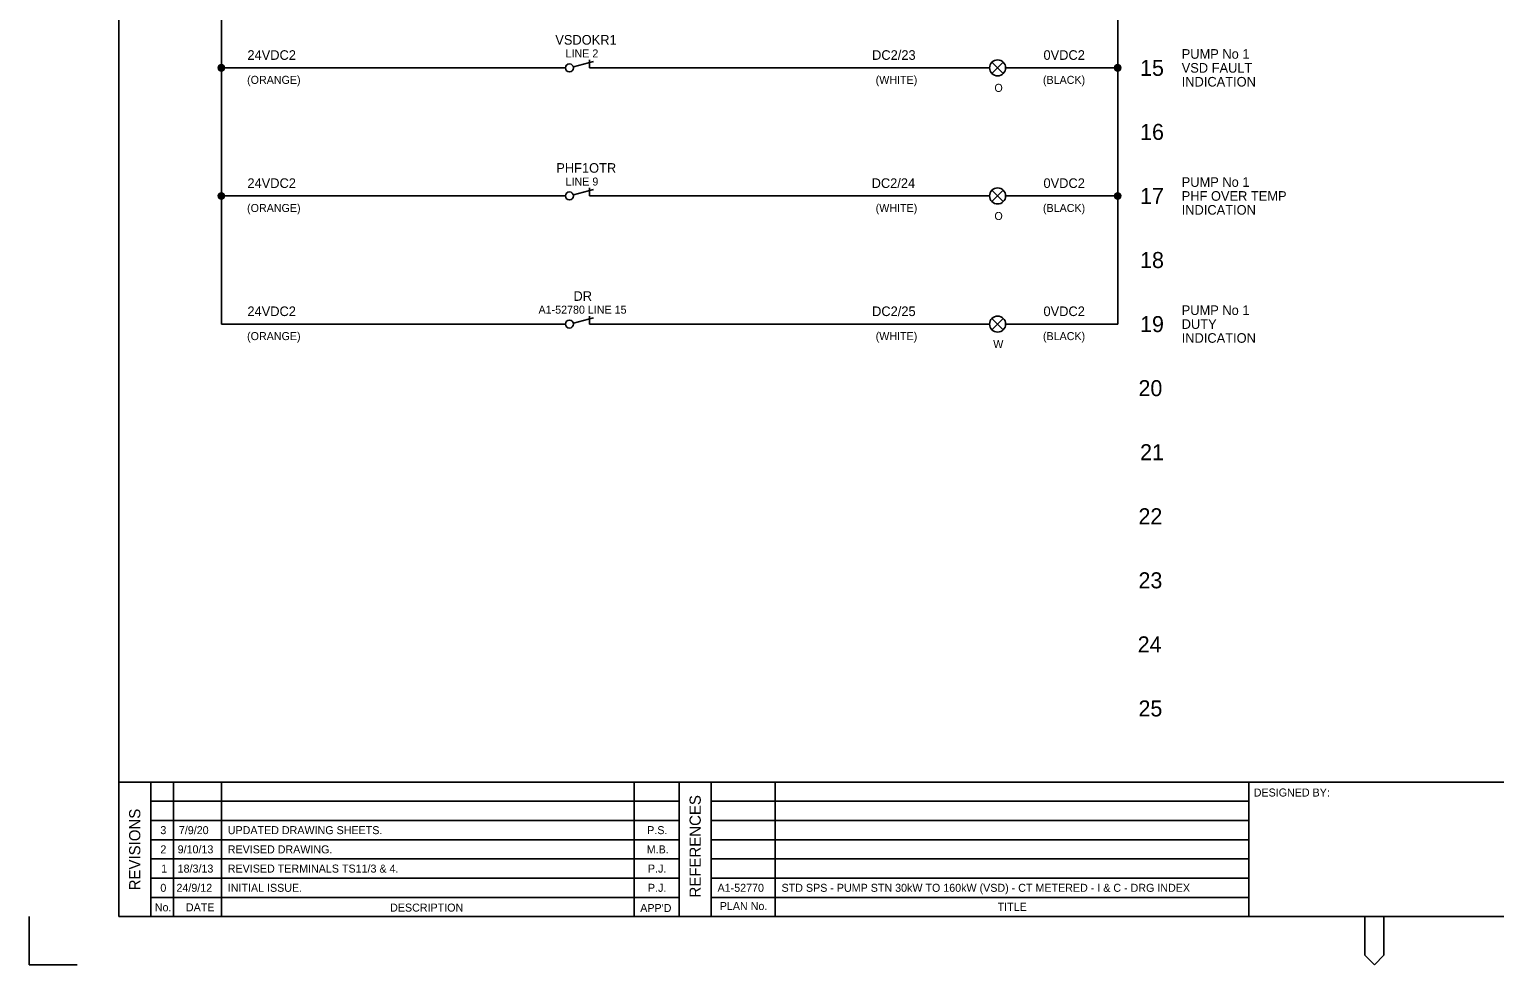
# Model space of a CAD drawing. Extents: x 0 to 841, y 0 to 594.
# Drawn here: x 0 to 457.8, y 0 to 292 of the extents above; entities that cross this region are included whole.
import ezdxf

# ---------------------------------------------------------------- set-up
doc = ezdxf.new("R2010")
doc.units = 0
for name, color, linetype in [('A1BORDER', 7, 'Continuous'), ('Level 1', 7, 'Continuous'), ('Level 10', 7, 'Continuous'), ('Level 5', 7, 'Continuous'), ('Level 6', 7, 'Continuous')]:
    doc.layers.add(name, color=color, linetype=linetype)

msp = doc.modelspace()

# ---------------------------------------------------------------- linework, layer by layer
at = {"layer": 'A1BORDER'}
for p, q in [((28, 581), (28, 15)), ((28, 57), (829, 57)), ((38, 15), (38, 57)), ((45, 15), (45, 57)), ((60, 15), (60, 57)), ((189, 15), (189, 57)), ((203, 15), (203, 57)), ((213, 15), (213, 57)), ((233, 15), (233, 57)), ((381, 15), (381, 57)), ((203, 51), (38, 51)), ((213, 51), (381, 51)), ((203, 45), (38, 45)), ((213, 45), (381, 45)), ((203, 39), (38, 39)), ((213, 39), (381, 39)), ((203, 33), (38, 33)), ((213, 33), (381, 33)), ((38, 27), (203, 27)), ((213, 27), (381, 27)), ((203, 21), (38, 21)), ((213, 21), (381, 21)), ((0, 0), (0, 15)), ((829, 15), (28, 15)), ((417.19, 15), (417.19, 3)), ((423.19, 15), (423.19, 3)), ((0, 0), (15, 0)), ((417.19, 3), (420.19, 0)), ((423.19, 3), (420.19, 0))]:
    msp.add_line(p, q, dxfattribs=at)
at = {"layer": 'Level 1'}
for p, q in [((60, 200), (60, 560)), ((340, 200), (340, 560)), ((60, 280), (167.5, 280)), ((175, 280), (177.5, 280)), ((305, 280), (340, 280)), ((60, 240), (167.5, 240)), ((175, 240), (177.5, 240)), ((305, 240), (340, 240)), ((60, 200), (167.5, 200)), ((175, 200), (177.5, 200)), ((305, 200), (340, 200))]:
    msp.add_line(p, q, dxfattribs=at)
at = {"layer": 'Level 10'}
for p, q in [((59.1, 280.44), (59.1, 279.56)), ((59.4, 280.8), (59.4, 279.2)), ((59.7, 280.95), (59.7, 279.05)), ((60, 281), (60, 279.01)), ((60.3, 280.95), (60.3, 279.05)), ((60.6, 280.8), (60.6, 279.2)), ((60.9, 280.44), (60.9, 279.56)), ((61, 280), (61, 280)), ((169.96, 280.32), (176.25, 282)), ((175, 282.5), (175, 280)), ((304.27, 281.77), (300.73, 278.23)), ((300.73, 281.77), (304.27, 278.23)), ((339.1, 280.44), (339.1, 279.56)), ((339.4, 280.8), (339.4, 279.2)), ((339.7, 280.95), (339.7, 279.05)), ((340, 281), (340, 279.01)), ((340.3, 280.95), (340.3, 279.05)), ((340.6, 280.8), (340.6, 279.2)), ((340.9, 280.44), (340.9, 279.56)), ((341, 280), (341, 280)), ((59.1, 240.44), (59.1, 239.56)), ((59.4, 240.8), (59.4, 239.2)), ((59.7, 240.95), (59.7, 239.05)), ((60, 241), (60, 239.01)), ((60.3, 240.95), (60.3, 239.05)), ((60.6, 240.8), (60.6, 239.2)), ((60.9, 240.44), (60.9, 239.56)), ((61, 240), (61, 240)), ((169.96, 240.32), (176.25, 242)), ((175, 242.5), (175, 240)), ((304.27, 241.77), (300.73, 238.23)), ((300.73, 241.77), (304.27, 238.23)), ((339.1, 240.44), (339.1, 239.56)), ((339.4, 240.8), (339.4, 239.2)), ((339.7, 240.95), (339.7, 239.05)), ((340, 241), (340, 239.01)), ((340.3, 240.95), (340.3, 239.05)), ((340.6, 240.8), (340.6, 239.2)), ((340.9, 240.44), (340.9, 239.56)), ((341, 240), (341, 240)), ((169.96, 200.32), (176.25, 202)), ((175, 202.5), (175, 200)), ((304.27, 201.77), (300.73, 198.23)), ((300.73, 201.77), (304.27, 198.23))]:
    msp.add_line(p, q, dxfattribs=at)
for centre, radius in [((60, 280), 1), ((168.75, 280), 1.25), ((302.5, 280), 2.5), ((340, 280), 1), ((60, 240), 1), ((168.75, 240), 1.25), ((302.5, 240), 2.5), ((340, 240), 1), ((302.5, 200), 2.5), ((168.75, 200), 1.25)]:
    msp.add_circle(centre, radius, dxfattribs=at)
at = {"layer": 'Level 6'}
for p, q in [((177.5, 280), (300, 280)), ((177.5, 240), (300, 240)), ((177.5, 200), (300, 200))]:
    msp.add_line(p, q, dxfattribs=at)

# ---------------------------------------------------------------- texts
at = {"layer": 'A1BORDER'}
for s, p in [('DESIGNED BY:', (382.5, 52.5)), ('No.', (39.21, 16.65)), ('DATE', (48.92, 16.65)), ('DESCRIPTION', (112.71, 16.57)), ("APP'D", (190.85, 16.44)), ('PLAN No.', (215.69, 17.06)), ('TITLE', (302.5, 16.81))]:
    msp.add_text(s, height=2.5, dxfattribs=at).set_placement(p)
for s, p in [('REFERENCES', (209.76, 20.96)), ('REVISIONS', (34.68, 23.2))]:
    msp.add_text(s, height=3.5, rotation=90, dxfattribs=at).set_placement(p)
at = {"layer": 'Level 1'}
for s, height, p in [('15', 5, (347.01, 277.5)), ('16', 5, (347.01, 257.5)), ('17', 5, (347.01, 237.5)), ('18', 5, (347.01, 217.5)), ('19', 5, (347.01, 197.5)), ('20', 5, (346.51, 177.5)), ('21', 5, (347.01, 157.5)), ('22', 5, (346.51, 137.5)), ('23', 5, (346.51, 117.5)), ('24', 5, (346.26, 97.5)), ('25', 5, (346.51, 77.5)), ('3', 2.5, (40.94, 40.75)), ('7/9/20', 2.5, (46.72, 40.75)), ('UPDATED DRAWING SHEETS.', 2.5, (62, 40.75)), ('P.S.', 2.5, (193.02, 40.75)), ('2', 2.5, (40.94, 34.75)), ('9/10/13', 2.5, (46.34, 34.75)), ('REVISED DRAWING.', 2.5, (62, 34.75)), ('M.B.', 2.5, (192.89, 34.75)), ('1', 2.5, (41.19, 28.75)), ('18/3/13', 2.5, (46.34, 28.75)), ('REVISED TERMINALS TS11/3 & 4.', 2.5, (62, 28.75)), ('P.J.', 2.5, (193.26, 28.75)), ('0', 2.5, (40.94, 22.75)), ('24/9/12', 2.5, (45.97, 22.75)), ('INITIAL ISSUE.', 2.5, (62, 22.75)), ('P.J.', 2.5, (193.26, 22.75)), ('A1-52770', 2.5, (215, 22.75)), ('STD SPS - PUMP STN 30kW TO 160kW (VSD) - CT METERED - I & C - DRG INDEX', 2.5, (235, 22.75))]:
    msp.add_text(s, height=height, dxfattribs=at).set_placement(p)
at = {"layer": 'Level 5'}
for s, height, p in [('VSDOKR1', 3, (164.32, 287.25)), ('24VDC2', 3, (68.13, 282.5)), ('LINE 2', 2.5, (167.53, 283.25)), ('DC2/23', 3, (263.28, 282.5)), ('0VDC2', 3, (316.82, 282.5)), ('PUMP No 1', 3, (360, 282.84)), ('VSD FAULT', 3, (360, 278.5)), ('(ORANGE)', 2.5, (68.03, 275)), ('(WHITE)', 2.5, (264.4, 275)), ('O', 2.5, (301.5, 272.5)), ('(BLACK)', 2.5, (316.65, 275)), ('INDICATION', 3, (360, 274.16)), ('PHF1OTR', 3, (164.62, 247.25)), ('24VDC2', 3, (68.13, 242.5)), ('LINE 9', 2.5, (167.53, 243.25)), ('DC2/24', 3, (263.13, 242.5)), ('0VDC2', 3, (316.82, 242.5)), ('PUMP No 1', 3, (360, 242.84)), ('PHF OVER TEMP', 3, (360, 238.5)), ('(ORANGE)', 2.5, (68.03, 235)), ('(WHITE)', 2.5, (264.4, 235)), ('O', 2.5, (301.5, 232.5)), ('(BLACK)', 2.5, (316.65, 235)), ('INDICATION', 3, (360, 234.16)), ('DR', 3, (170, 207.25)), ('24VDC2', 3, (68.13, 202.5)), ('A1-52780 LINE 15', 2.5, (159.07, 203.25)), ('DC2/25', 3, (263.28, 202.5)), ('0VDC2', 3, (316.82, 202.5)), ('PUMP No 1', 3, (360, 202.84)), ('DUTY', 3, (360, 198.5)), ('(ORANGE)', 2.5, (68.03, 195)), ('(WHITE)', 2.5, (264.4, 195)), ('(BLACK)', 2.5, (316.65, 195)), ('INDICATION', 3, (360, 194.16)), ('W', 2.5, (301.13, 192.5))]:
    msp.add_text(s, height=height, dxfattribs=at).set_placement(p)

doc.saveas('drawing.dxf')
